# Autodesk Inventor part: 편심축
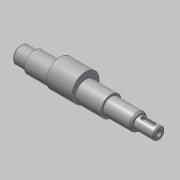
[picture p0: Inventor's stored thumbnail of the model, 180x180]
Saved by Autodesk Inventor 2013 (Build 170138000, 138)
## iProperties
Created: 2019-05
Part Number: 편심축
Material: 강철, 연강
Document SubType Name: Modeling
Designer: mduedu
Density: 7.86 g/cm^3
Mass: 359.395 g
Surface Area: 100.518 cm^2
Volume: 45.7245 cm^3
Author: mduedu
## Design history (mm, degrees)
sketch "스케치1"
  geometry: L1 (0, 0)-(14, 0); L2 (14, 0)-(14, 8.5); L3 (14, 8.5)-(0, 8.5); L4 (0, 8.5)-(0, 0); L5 (14, 0)-(92, 0); L6 (92, 0)-(92, 10.5); L7 (92, 10.5)-(14, 10.5); L8 (14, 10.5)-(14, 0); L9 (92, 8.5)-(92, 0); L10 (92, 0)-(121, 0); L11 (121, 0)-(121, 8.5); L12 (121, 8.5)-(92, 8.5); L13 (92, 8.5)-(92, 0); L14 (121, 0)-(141, 0); L15 (141, 0)-(141, 6); L16 (141, 6)-(121, 6); L17 (121, 6)-(121, 0)
  constraints: 34 end point, 8 parallel, 4 horizontal, 4 perpendicular
  dimensions: "d2" = 14 distance of L2.end L3.end; "d5" = 17 diameter of L3 L1; "d6" = 21 diameter of L7 L5; "d11" = 78 distance of L6.end L7.end (derived); "d12" = 141 distance between parallel lines of L15 L4; "d13" = 20 distance of L15.end L16.end; "d14" = 49 distance between parallel lines of L15 L6; "d15" = 12 diameter of L16 L14; "d16" = 17 diameter of L12 L10
revolve "회전1" sketch "스케치1" stored, may be unused: angle "d17" = 90 deg
node "작업 평면1"
sketch "스케치2"
  geometry: C1 r 14 at (0, 3.5); C2 r 10.5 at (0, 0) reference; 1 further point
  constraints: 1 centre point, 1 tangent, 1 vertical alignment
  dimensions: "d18" = 28 diameter of C1; "d21" = 3.5 distance of C1.centre point (0, 0) (derived)
extrude "돌출1" join sketch "스케치2" stored distance "d19" = 26; taper "d20" = 0 deg
hole "구멍2" diameter "d45" = 3.242; stored, may be unused: countersink angle "d49" = 60 deg, drill point angle "d51" = 118 deg; dims "d43" = 10, "d44" = 10, "d46" = 8, "d47" = 6.7, "d48" = 2, "d50" = 10
chamfer "모따기3" distance "d52" = 2; stored, may be unused: second distance "d53" = 2, angle "d54" = 30 deg
node "작업 평면2"
sketch "스케치3" dims "d32" = 14
  geometry: L1 (6, -2)-(-4, -2); L2 (-4, -2)-(-4, 2); L3 (-4, 2)-(6, 2); L4 (6, 2)-(6, -2); L5 (10, 8.5)-(10, -8.5) reference; 3 further points
  constraints: 8 end point, 2 midpoint, 2 parallel, 2 vertical alignment, 1 horizontal, 1 horizontal alignment, 1 perpendicular, 4 other
  dimensions: "d31" = 2 dimension on L5; "d33" = 4 distance between parallel lines of L3 L1
extrude "돌출2" cut sketch "스케치3" distance "d34" = 2.5; taper "d35" = 0 deg
chamfer "모따기1" distance "d36" = 1; stored, may be unused: second distance "d37" = 2, angle "d38" = 45 deg
fillet "모깎기1" dims "d39" = 0.3
chamfer "모따기2" distance "d40" = 1.82; stored, may be unused: second distance "d41" = 2, angle "d42" = 30 deg
fillet "모깎기2" dims "d55" = 2
fillet "모깎기3" dims "d56" = 0.5
node "솔리드1"
